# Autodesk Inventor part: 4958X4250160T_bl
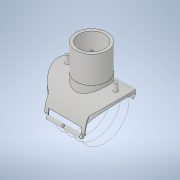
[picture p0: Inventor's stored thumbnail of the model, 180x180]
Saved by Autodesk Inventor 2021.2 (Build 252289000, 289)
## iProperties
Created: 2020-06
Part Number: 4958X4250160T_bl
Material: Generic
Description: Plasson Branch Saddle 250x160
Document SubType Name: Modeling
Designer: KIM
Density: 1 g/cm^3
Appearance: Default
Author: KIM
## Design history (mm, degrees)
derived "4958X4.ipt"
feature "Solid1::4958X4.ipt" dims "ScaleForDerivedMember" = 10
tag "TaggingFeature1"
body "Solid1"
other parameters: "d0" = 338 [user parameter], "d3" = 274.6 [user parameter], "d4" = 167 [user parameter], "d7" = 131 [user parameter], "d9" = 137 [user parameter], "d10" = 0.5 [user parameter], "d11" = 1 [user parameter], "d12" = 41.75 [user parameter], "d13" = 16 [user parameter], "d14" = 8 [user parameter], "d16" = 10 deg [user parameter], "d17" = 10 deg [user parameter], "d19" = 0 [user parameter], "d23" = 0 [user parameter], "d26" = 0 [user parameter], "d27" = 202.8 [user parameter], "d28" = 0 [user parameter], "d29" = 169 [user parameter], "d30" = 0 [user parameter], "d31" = 1 [user parameter], "d32" = 1 [user parameter], "d33" = 19.2 [user parameter], "d34" = 9.6 [user parameter], "d35" = 45 deg [user parameter], "d36" = 169 [user parameter], "d37" = 0 [user parameter], "d38" = 5 [user parameter], "d39" = 85 deg [user parameter], "d40" = 41.75 [user parameter], "d41" = 16 [user parameter], "d42" = 122.90909 [user parameter], "d49" = 3 [user parameter], "d50" = 6 [user parameter], "d51" = 5 [user parameter], "d54" = 0 [user parameter], "d57" = 35 deg [user parameter], "d60" = 21.125 [user parameter], "d61" = 1 [user parameter], "d62" = 90 deg [user parameter], "d63" = 2 [user parameter], "d64" = 0 [user parameter], "d65" = 0 [user parameter], "d68" = 42.25 [user parameter], "d70" = 0.57711 [user parameter], "d71" = 10 deg [user parameter], "d73" = 4.305 [user parameter], "B" = 291 [user parameter], "L" = 338 [user parameter], "LS" = 137 [user parameter], "H1" = 167 [user parameter], "Dt" = 16 [user parameter], "di" = 131 [user parameter], "d72" = 12.3 [user parameter]
